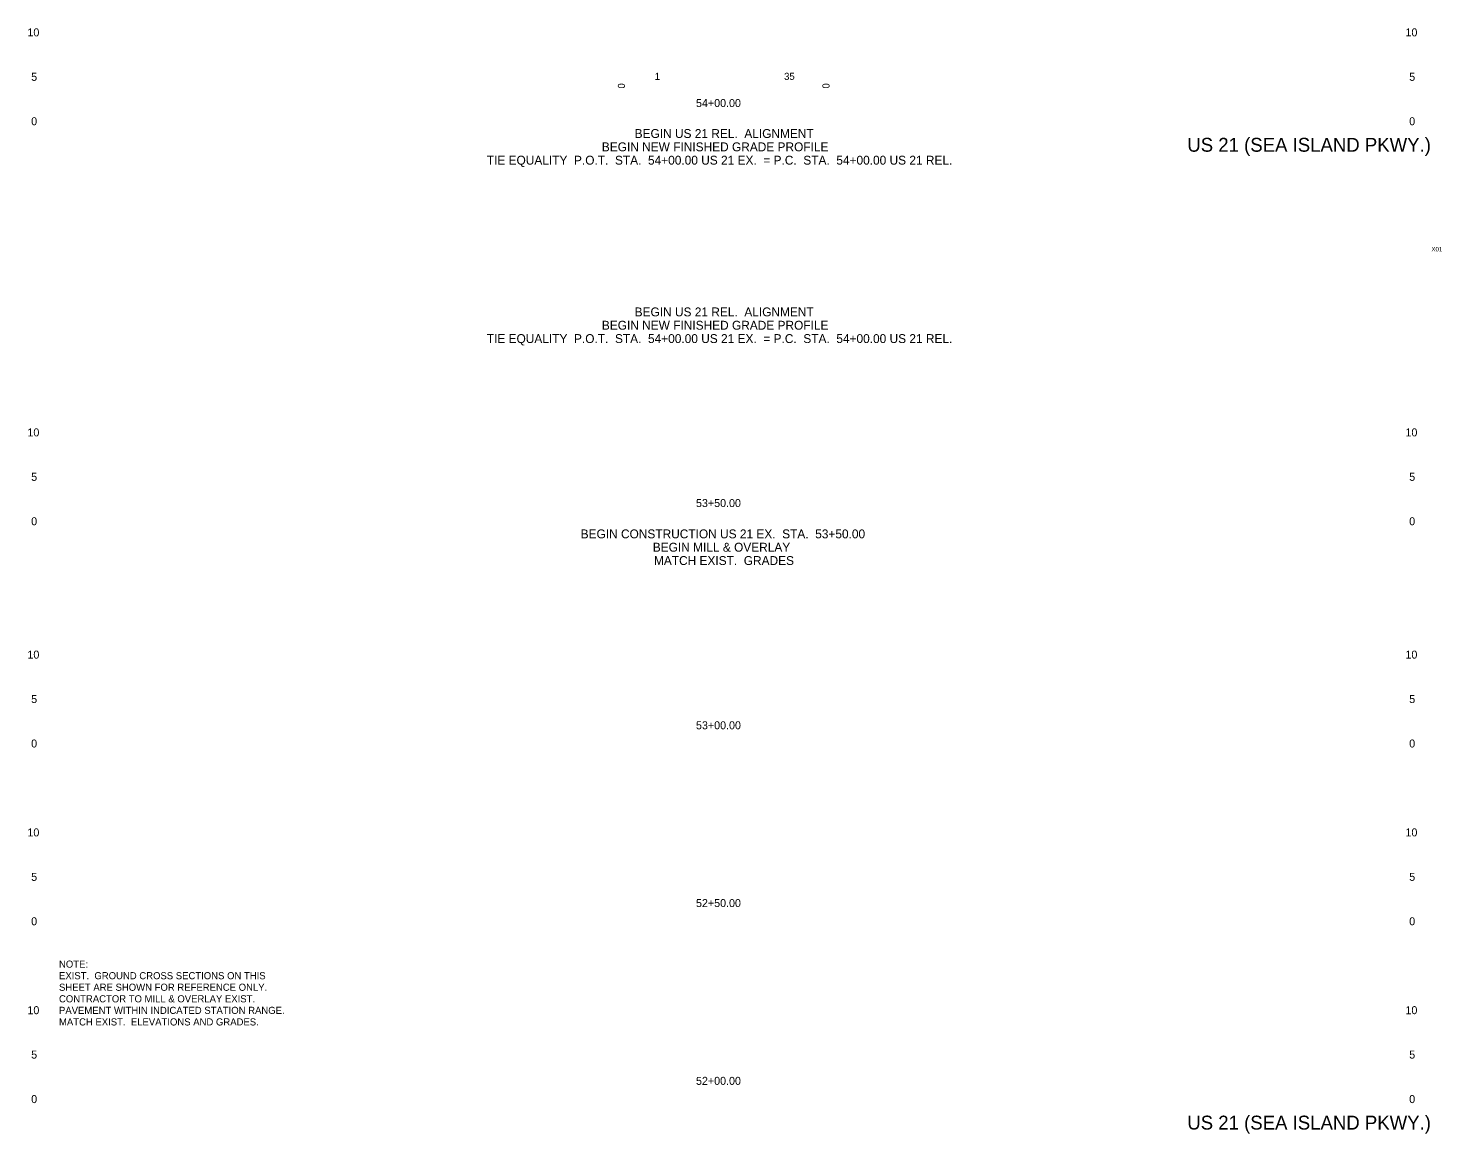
# Model space of a CAD drawing. Extents: x 971 to 1131, y 2203 to 6043.
# Drawn here: x 971.5 to 1130.5, y 2203.4 to 2327.8 of the extents above; entities that cross this region are included whole.
import ezdxf

# ---------------------------------------------------------------- set-up
doc = ezdxf.new("R2010")
doc.units = 0
for name, color, linetype in [('RD_SHT_Misc1', 7, 'Continuous'), ('RD_SHT_TX', 7, 'Continuous'), ('RD_TX_StaOff', 7, 'Continuous'), ('RD_XS_TX_Station', 7, 'Continuous')]:
    doc.layers.add(name, color=color, linetype=linetype)

msp = doc.modelspace()

# ---------------------------------------------------------------- texts
at = {"layer": 'RD_SHT_Misc1'}
for s, rotation, p in [('1', 360, (1041.98, 2321.97)), ('0', 90, (1038.63, 2321)), ('0', 90, (1061.64, 2321))]:
    msp.add_text(s, height=0.8, rotation=rotation, dxfattribs=at).set_placement(p)
msp.add_text('35', height=0.8, dxfattribs=at).set_placement((1056.53, 2321.97))
at = {"layer": 'RD_SHT_TX'}
for s, height, p in [('10', 0.9, (971.42, 2326.87)), ('10', 0.9, (1126.42, 2326.87)), ('5', 0.9, (971.84, 2321.87)), ('5', 0.9, (1126.84, 2321.87)), ('0', 0.9, (971.84, 2316.87)), ('0', 0.9, (1126.84, 2316.87)), ('US 21 (SEA ISLAND PKWY.)', 1.5625, (1101.88, 2313.89)), ('10', 0.9, (971.42, 2281.87)), ('10', 0.9, (1126.42, 2281.87)), ('5', 0.9, (971.84, 2276.87)), ('5', 0.9, (1126.84, 2276.87)), ('0', 0.9, (971.84, 2271.87)), ('0', 0.9, (1126.84, 2271.87)), ('10', 0.9, (971.42, 2256.87)), ('10', 0.9, (1126.42, 2256.87)), ('5', 0.9, (971.84, 2251.87)), ('5', 0.9, (1126.84, 2251.87)), ('0', 0.9, (971.84, 2246.87)), ('0', 0.9, (1126.84, 2246.87)), ('10', 0.9, (971.42, 2236.87)), ('10', 0.9, (1126.42, 2236.87)), ('5', 0.9, (971.84, 2231.87)), ('5', 0.9, (1126.84, 2231.87)), ('0', 0.9, (971.84, 2226.87)), ('0', 0.9, (1126.84, 2226.87)), ('10', 0.9, (971.42, 2216.87)), ('10', 0.9, (1126.42, 2216.87)), ('5', 0.9, (971.84, 2211.87)), ('5', 0.9, (1126.84, 2211.87)), ('0', 0.9, (971.84, 2206.87)), ('0', 0.9, (1126.84, 2206.87)), ('US 21 (SEA ISLAND PKWY.)', 1.5625, (1101.88, 2203.89))]:
    msp.add_text(s, height=height, dxfattribs=at).set_placement(p)
msp.add_text('X01', height=0.5, rotation=360, dxfattribs=at).set_placement((1129.34, 2302.68))
at = {"layer": 'RD_TX_StaOff'}
for s, height, p in [('BEGIN US 21 REL.  ALIGNMENT', 1, (1039.72, 2315.44)), ('BEGIN NEW FINISHED GRADE PROFILE', 1, (1036.03, 2313.94)), ('TIE EQUALITY  P.O.T.  STA.  54+00.00 US 21 EX.  = P.C.  STA.  54+00.00 US 21 REL.', 1, (1023.09, 2312.44)), ('BEGIN US 21 REL.  ALIGNMENT', 1, (1039.72, 2295.37)), ('BEGIN NEW FINISHED GRADE PROFILE', 1, (1036.03, 2293.87)), ('TIE EQUALITY  P.O.T.  STA.  54+00.00 US 21 EX.  = P.C.  STA.  54+00.00 US 21 REL.', 1, (1023.09, 2292.37)), ('BEGIN CONSTRUCTION US 21 EX.  STA.  53+50.00', 1, (1033.65, 2270.4)), ('BEGIN MILL & OVERLAY', 1, (1041.76, 2268.9)), ('MATCH EXIST.  GRADES', 1, (1041.89, 2267.4)), ('NOTE:', 0.8, (974.97, 2222.1)), ('EXIST.  GROUND CROSS SECTIONS ON THIS', 0.8, (974.97, 2220.8)), ('SHEET ARE SHOWN FOR REFERENCE ONLY.', 0.8, (974.97, 2219.5)), ('CONTRACTOR TO MILL & OVERLAY EXIST.', 0.8, (974.97, 2218.2)), ('PAVEMENT WITHIN INDICATED STATION RANGE.', 0.8, (974.97, 2216.9)), ('MATCH EXIST.  ELEVATIONS AND GRADES.', 0.8, (974.97, 2215.6))]:
    msp.add_text(s, height=height, dxfattribs=at).set_placement(p)
at = {"layer": 'RD_XS_TX_Station'}
for s, p in [('54+00.00', (1046.62, 2318.92)), ('53+50.00', (1046.62, 2273.92)), ('53+00.00', (1046.62, 2248.92)), ('52+50.00', (1046.62, 2228.92)), ('52+00.00', (1046.62, 2208.92))]:
    msp.add_text(s, height=0.9, dxfattribs=at).set_placement(p)

doc.saveas('drawing.dxf')
